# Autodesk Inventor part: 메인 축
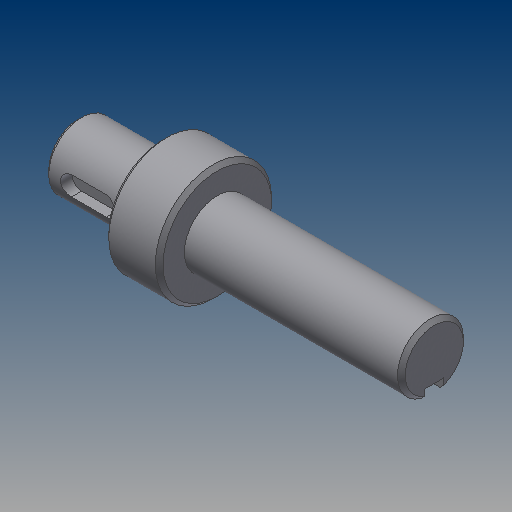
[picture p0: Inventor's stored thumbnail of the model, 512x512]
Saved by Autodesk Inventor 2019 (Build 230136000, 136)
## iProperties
Created: 2014-10
Part Number: 메인 축
Document SubType Name: Modeling
Designer: KYOUNG IL JANG
Density: 7.86 g/cm^3
Mass: 230.24 g
Surface Area: 74.3518 cm^2
Volume: 29.2926 cm^3
Material: 강철, 연강
Appearance: 금속-강(스테인리스, 브러시됨)
Author: SeoGD™ [www.esajin.kr]
Revision Number: 1
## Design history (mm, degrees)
sketch "스케치1"
  geometry: L1 (10.497, -57.5)-(102.497, -57.5); L2 (10.497, -66)-(32.497, -66); L3 (32.497, -72.5)-(46.5, -72.5); L4 (46.5, -66)-(102.497, -66); L5 (102.497, -66)-(102.497, -57.5); L6 (10.497, -66)-(10.497, -57.5); L7 (46.5, -69.749)-(46.5, -45.251) reference; L8 (46.5, -72.5)-(46.5, -66); L9 (32.497, -72.5)-(32.497, -66); L10 (32.497, -35)-(32.497, -80) reference; 2 further points
  constraints: 16 end point, 2 parallel, 2 perpendicular, 2 point on line, 1 collinear, 1 horizontal, 1 midpoint
  dimensions: "d0" = 17 diameter of L4 L1; "d1" = 30 diameter of L3 L1; "d2" = 22 distance of L2.start L2.end; "d3" = 55.99692 distance of L4.start L4.end (derived); "d5" = 17 diameter of L2 L1; "d19" = 70 distance between parallel lines of L5 L9
revolve "회전1" sketch "스케치1" stored, may be unused: angle "d4" = 90 deg
chamfer "모따기1" distance "d6" = 1; stored, may be unused: second distance "d7" = 2, angle "d8" = 45 deg
node "작업 평면1"
sketch "스케치2"
  geometry: L1 (-11, -7.5)-(-11, 7.5) reference; L2 (-4.5, 2.5)-(4.5, 2.5); L3 (4.5, -2.5)-(-4.5, -2.5); A1 r 2.5 centre (4.5, 0) between (4.5, -2.5) and (4.5, 2.5); A2 r 2.5 centre (-4.5, 0) between (-4.5, 2.5) and (-4.5, -2.5); 2 further points
  constraints: 4 end point, 4 point on circle, 4 tangent, 2 centre point, 1 horizontal alignment, 1 midpoint, 1 parallel, 1 perpendicular
  dimensions: "d9" = 5 distance between parallel lines of L3 L2; "d10" = 14 dimension on A1 A2; "d11" = 4 distance edge to line of A2 L1
extrude "돌출1" cut sketch "스케치2" distance "d12" = 3; taper "d13" = 0 deg
node "작업 평면2"
sketch "스케치3"
  geometry: L1 (27.998, 7.5)-(27.998, -7.5) reference; L2 (27.998, 2.5)-(12.498, 2.5); L3 (12.498, -2.5)-(27.998, -2.5); A1 r 2.5 centre (12.498, 0) between (12.498, 2.5) and (12.498, -2.5); 2 further points
  constraints: 4 end point, 2 perpendicular, 2 point on circle, 2 point on line, 2 tangent, 1 centre point, 1 horizontal alignment, 1 midpoint
  dimensions: "d14" = 5 distance between parallel lines of L3 L2; "d15" = 18 dimension on A1 L1
extrude "돌출2" cut sketch "스케치3" distance "d16" = 3; taper "d17" = 0 deg
node "솔리드1"
node "참조4"
node "참조5"
